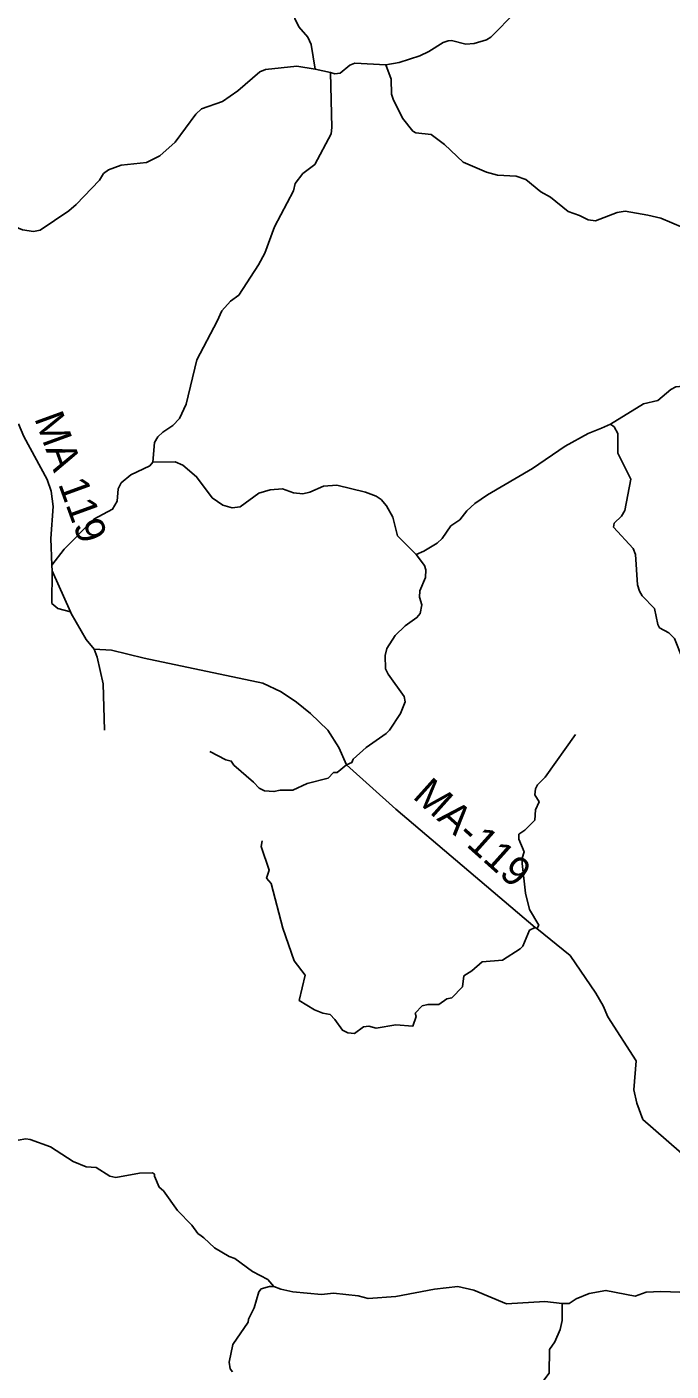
# Model space of a CAD drawing. Extents: x 332 to 501, y 9447 to 9559.
# Drawn here: x 475.23 to 483.56, y 9494.28 to 9511.64 of the extents above; entities that cross this region are included whole.
import ezdxf

# ---------------------------------------------------------------- set-up
doc = ezdxf.new("R2010")
doc.units = 0
for name, color, linetype in [('Level 2', 7, 'Continuous'), ('Level 31', 7, 'Continuous'), ('Level 4', 7, 'Continuous'), ('Level 5', 7, 'Continuous'), ('Level 6', 7, 'Continuous')]:
    doc.layers.add(name, color=color, linetype=linetype)

msp = doc.modelspace()

# ---------------------------------------------------------------- linework, layer by layer
at = {"layer": 'Level 2'}
for points in [[(479.3623, 9502.1083), (479.2662, 9502.3325), (479.1221, 9502.5596)], [(480, 9501.5363), (479.3623, 9502.1083)], [(481.8041, 9500.0098), (480, 9501.5363)], [(481.8168, 9500), (481.8041, 9500.0098)], [(481.8249, 9499.9937), (481.8168, 9500)], [(484, 9496.8247), (483.1916, 9497.5294), (483.1148, 9497.7406), (483.0763, 9497.9134), (483.1084, 9498.2847), (482.7391, 9498.8538), (482.6815, 9498.9947), (482.5855, 9499.1612), (482.2526, 9499.648), (481.8249, 9499.9937)], [(484, 9495.2529), (483.7972, 9495.2917), (483.4254, 9495.3065), (483.2376, 9495.2991), (483.0958, 9495.2475), (482.7167, 9495.3212), (482.4994, 9495.2807), (482.3338, 9495.2107), (482.2417, 9495.1518), (482.1514, 9495.1518)]]:
    msp.add_lwpolyline(points, dxfattribs=at)
at = {"layer": 'Level 4'}
for points in [[(475.1276, 9506.5158), (475.1968, 9506.3519), (475.4947, 9505.794), (475.5502, 9505.6451), (475.5755, 9505.4482), (475.5452, 9505.0342), (475.557, 9504.6897)], [(475.557, 9504.6897), (475.5629, 9504.6152)], [(475.5629, 9504.6152), (475.7988, 9504.0846)], [(475.7988, 9504.0846), (475.807, 9504.0668)], [(475.807, 9504.0668), (475.9996, 9503.7272), (476.1056, 9503.6029)], [(476.1056, 9503.6029), (476.3278, 9503.5928), (476.7518, 9503.4893), (478.2815, 9503.1637), (478.5213, 9503.0533), (478.7176, 9502.9201), (478.8999, 9502.7712), (479.1221, 9502.5596)], [(475.9999, 9496.9153), (475.8325, 9496.9871), (475.5416, 9497.175), (475.2766, 9497.2707), (475.2213, 9497.2781), (474.8211, 9497.2098), (474.5634, 9497.2098), (474.453, 9497.254), (474.2763, 9497.3718), (474.1916, 9497.4639), (474.129, 9497.5818), (473.9965, 9497.6518), (473.8087, 9497.6665), (473.4811, 9497.4455), (473.3319, 9497.3866), (472.9896, 9497.2761), (472.8165, 9497.254), (472.6803, 9497.2577), (472.4226, 9497.125), (472.2496, 9497.1066), (471.9999, 9497.0062)], [(476.8832, 9496.7968), (476.8832, 9496.8225), (476.8559, 9496.8397), (476.6903, 9496.8361), (476.3847, 9496.7808), (476.3074, 9496.7955), (476.1307, 9496.9097), (475.9999, 9496.9153)], [(477.4861, 9496.026), (477.4428, 9496.0563), (477.3655, 9496.1632), (477.1814, 9496.351), (477.001, 9496.6052), (476.9421, 9496.6531), (476.8832, 9496.7968)], [(477.522, 9496), (477.4861, 9496.026)], [(478.4263, 9495.373), (478.3474, 9495.4612), (478.1486, 9495.5643), (477.9214, 9495.7322), (477.8478, 9495.7579), (477.66, 9495.8685), (477.522, 9496)], [(480, 9495.2429), (479.6462, 9495.2144), (479.5137, 9495.2512), (479.1971, 9495.2844), (479.0424, 9495.266), (478.6706, 9495.3028), (478.5167, 9495.3359), (478.4263, 9495.373)], [(482.1514, 9495.1518), (481.9266, 9495.1775), (481.4333, 9495.1481), (481.0099, 9495.3249), (480.8037, 9495.3691), (480.5018, 9495.3359), (480, 9495.2429)]]:
    msp.add_lwpolyline(points, dxfattribs=at)
at = {"layer": 'Level 5'}
for points in [[(479.8705, 9511.1532), (480.0434, 9511.1808), (480.3122, 9511.2704), (480.4296, 9511.3234), (480.6115, 9511.442), (480.6772, 9511.4635), (480.7226, 9511.466), (480.9068, 9511.4206), (481.0141, 9511.4269), (481.1744, 9511.4761), (481.2274, 9511.5108), (481.5505, 9511.8377), (481.6735, 9511.9073)], [(474.888, 9509.1414), (475.1766, 9509.0213), (475.3212, 9509.0005), (475.4064, 9509.0187), (475.7749, 9509.2648), (475.8733, 9509.3482), (476.1712, 9509.6612), (476.2267, 9509.7483), (476.2886, 9509.7962), (476.4515, 9509.8555), (476.7821, 9509.8908), (476.9537, 9509.9754), (477.1493, 9510.1534), (477.4169, 9510.515), (477.4926, 9510.5844), (477.7609, 9510.6771), (477.9596, 9510.8167), (478.2455, 9511.0621), (478.3169, 9511.0937)], [(478.3169, 9511.0937), (478.7245, 9511.1341), (478.9589, 9511.0982)], [(478.9589, 9511.0982), (479.1592, 9511.0533)], [(479.1592, 9511.0533), (479.2155, 9511.0369), (479.2836, 9511.0445), (479.4073, 9511.148), (479.4717, 9511.1744), (479.8705, 9511.1532)], [(481.6816, 9509.6709), (481.5566, 9509.712), (481.3146, 9509.7284), (481.1741, 9509.7659), (480.8712, 9509.8947), (480.6323, 9510.1243), (480.4589, 9510.2516), (480.259, 9510.2719), (480.2215, 9510.2937), (480.0872, 9510.4616), (479.967, 9510.7083), (479.9451, 9510.7731), (479.942, 9510.9667), (479.8705, 9511.1532)], [(481.8762, 9509.5139), (481.6816, 9509.6709)], [(482.8611, 9509.2465), (482.5826, 9509.1389), (482.4873, 9509.1483), (482.3764, 9509.2076), (482.2296, 9509.2568), (482.0001, 9509.4411), (481.8762, 9509.5139)], [(483.2561, 9509.2105), (482.9652, 9509.26), (482.8611, 9509.2465)], [(485.4436, 9507.794), (485.1247, 9508.2535), (484.9326, 9508.5822), (484.8421, 9508.6806), (484.7468, 9508.7477), (484.141, 9508.9515), (483.71, 9509.0491), (483.4258, 9509.1732), (483.2561, 9509.2105)], [(480.2657, 9504.8276), (480.3656, 9504.8698), (480.5358, 9504.9729), (480.5999, 9505.0322), (480.714, 9505.1985), (480.8295, 9505.275), (480.9185, 9505.3921)], [(480.2657, 9504.8276), (480.0252, 9505.0689), (479.9612, 9505.3102)], [(482.8162, 9505.1792), (483.0684, 9504.9056), (483.0997, 9504.826), (483.1247, 9504.434), (483.1497, 9504.352), (483.1856, 9504.2942), (483.3433, 9504.1287), (483.387, 9503.9218), (483.4104, 9503.8797), (483.5307, 9503.8156), (483.6025, 9503.7407), (483.8008, 9503.2418)], [(480.311, 9504.3584), (480.3844, 9504.5286), (480.3891, 9504.627), (480.3703, 9504.6832), (480.2657, 9504.8276)], [(475.6339, 9504.1314), (475.5584, 9504.1949), (475.5629, 9504.6152)], [(479.9198, 9502.5598), (480.0635, 9502.7717), (480.1213, 9502.9232), (480.1103, 9502.9935), (479.9011, 9503.2832), (479.8699, 9503.3503), (479.862, 9503.5205), (479.8854, 9503.6119), (479.9916, 9503.7821), (480.1228, 9503.9039), (480.2743, 9504.0124), (480.3149, 9504.064), (480.3383, 9504.1748), (480.3055, 9504.2748), (480.311, 9504.3584)], [(475.7988, 9504.0846), (475.6339, 9504.1314)], [(476.1056, 9503.6029), (476.143, 9503.4989), (476.2185, 9503.1573), (476.2383, 9502.5588)], [(479.9198, 9502.5598), (479.8779, 9502.5155), (479.6183, 9502.3339), (479.4519, 9502.1849), (479.4344, 9502.1411), (479.3623, 9502.1083)], [(482.3225, 9502.5013), (481.9306, 9501.9492), (481.8343, 9501.8528), (481.808, 9501.8002), (481.7993, 9501.7213), (481.8518, 9501.6337), (481.808, 9501.5285), (481.7993, 9501.397), (481.6679, 9501.2656), (481.589, 9501.213), (481.589, 9501.1516), (481.6591, 9500.9851), (481.6328, 9500.9062), (481.6328, 9500.8361), (481.6766, 9500.4505), (481.7292, 9500.2402), (481.8491, 9500.0374), (481.8286, 9500)], [(478.3045, 9501.773), (478.2345, 9501.8081), (478.1644, 9501.8869), (477.9104, 9502.106), (477.8753, 9502.1586), (477.8053, 9502.1761), (477.5975, 9502.2813)], [(479.3623, 9502.1083), (479.2417, 9502.0096), (479.1979, 9502.0096), (479.1278, 9501.9395), (478.8563, 9501.8694), (478.6724, 9501.7818), (478.506, 9501.7818), (478.4271, 9501.7642), (478.3045, 9501.773)], [(481.7305, 9499.9754), (481.6416, 9499.7687), (481.6066, 9499.7336), (481.3788, 9499.5846), (481.1161, 9499.5671), (480.9822, 9499.4488), (480.8784, 9499.3829), (480.8621, 9499.2428), (480.7232, 9499.0994), (480.6606, 9499.0851), (480.5555, 9499.015), (480.4154, 9499.015), (480.3408, 9498.9949), (480.2498, 9498.9008)], [(481.7305, 9499.9754), (481.8041, 9500.0098)], [(482.1514, 9495.1518), (482.1514, 9494.9312), (482.1232, 9494.816), (482.0577, 9494.6579), (481.9877, 9494.5585), (481.9837, 9494.2513), (481.5459, 9493.676), (481.4595, 9493.5958), (481.4194, 9493.4842), (481.4041, 9493.3245), (481.3651, 9493.2636), (481.345, 9493.1773), (481.4232, 9493.0348), (481.4418, 9492.8958), (481.5097, 9492.7647), (481.4808, 9492.4204), (481.5601, 9491.5793), (481.6136, 9491.3652), (481.7029, 9491.2251), (481.8417, 9491.0797), (481.8354, 9491.0358), (481.9326, 9490.9062), (481.9023, 9490.8503), (481.9598, 9490.8192)]]:
    msp.add_lwpolyline(points, dxfattribs=at)
at = {"layer": 'Level 6'}
for points in [[(478.0732, 9513.8135), (478.1943, 9513.6239), (478.2648, 9513.4721), (478.359, 9513.341), (478.5872, 9512.8945), (478.6398, 9512.7586), (478.6924, 9512.3825), (478.6954, 9511.7493), (478.747, 9511.6411), (478.8661, 9511.5091), (478.9078, 9511.4168), (478.9589, 9511.0982)], [(478.4347, 9509.0591), (478.6788, 9509.5262), (478.6999, 9509.6196), (478.7995, 9509.7477), (478.9563, 9509.8652), (479.166, 9510.2595), (479.176, 9510.3439), (479.1592, 9511.0533)], [(477.6947, 9507.8417), (477.7554, 9507.9729), (477.864, 9508.0985), (477.9725, 9508.1748), (478.2258, 9508.5696), (478.3096, 9508.7207), (478.4347, 9509.0591)], [(476.8629, 9506.0189), (476.883, 9506.272), (476.9252, 9506.3464), (476.9896, 9506.4087), (477.1222, 9506.4931), (477.2046, 9506.5845), (477.2911, 9506.7674), (477.4318, 9507.343), (477.6947, 9507.8417)], [(482.7767, 9506.5117), (483.201, 9506.7738), (483.3879, 9506.816), (483.5528, 9506.9576), (483.6212, 9506.9918), (483.7559, 9507.0038), (483.8664, 9506.9878), (484.0253, 9507.0531), (484.1801, 9507.0872), (484.4957, 9507.2229), (484.6283, 9507.2008), (484.8455, 9507.2419), (485.1088, 9507.3906), (485.2455, 9507.5182), (485.34, 9507.5805), (485.4023, 9507.6046), (485.5211, 9507.6134)], [(480.9185, 9505.3921), (481.0217, 9505.4857), (481.1846, 9505.5982), (481.7655, 9505.9378), (482.1897, 9506.2242), (482.4873, 9506.392), (482.6602, 9506.4601)], [(482.6602, 9506.4601), (482.7767, 9506.5117)], [(482.8162, 9505.1792), (482.8223, 9505.2298), (482.9157, 9505.3212), (482.9594, 9505.3967), (483.0388, 9505.8), (482.872, 9506.1358), (482.868, 9506.3881), (482.8223, 9506.4776), (482.7767, 9506.5117)], [(476.4134, 9505.6766), (476.4544, 9505.7515), (476.5765, 9505.8548), (476.8227, 9505.973), (476.8629, 9506.0189)], [(479.9612, 9505.3102), (479.8831, 9505.4552), (479.8107, 9505.5376), (479.7464, 9505.5818), (479.6118, 9505.6321), (479.2381, 9505.7215), (479.0673, 9505.7084), (478.8925, 9505.6301), (478.8, 9505.612), (478.6815, 9505.6251), (478.5388, 9505.6733), (478.38, 9505.6632), (478.2333, 9505.618), (477.9902, 9505.4432), (477.8857, 9505.4281), (477.7672, 9505.4623), (477.6305, 9505.5607), (477.4276, 9505.831), (477.2508, 9505.9797), (477.1523, 9506.0219), (476.8629, 9506.0189)], [(475.557, 9504.6897), (475.7172, 9504.8941), (476.0981, 9505.2816), (476.3422, 9505.4108), (476.4028, 9505.5141), (476.4134, 9505.6766)], [(478.2748, 9501.1281), (478.2607, 9501.057), (478.3658, 9500.7502), (478.3308, 9500.6451), (478.3921, 9500.575), (478.5414, 9500)], [(478.5414, 9500), (478.6899, 9499.5759), (478.8301, 9499.3918), (478.7512, 9499.0675), (478.9527, 9498.9449), (479.0578, 9498.901), (479.1541, 9498.8835), (479.2154, 9498.8222), (479.3118, 9498.6819), (479.3818, 9498.6469), (479.4694, 9498.6381), (479.5833, 9498.7258), (479.6534, 9498.7345), (479.7497, 9498.7082), (480, 9498.7499)], [(481.8286, 9500), (481.8249, 9499.9937)], [(480, 9498.7499), (480.2227, 9498.7345), (480.2665, 9498.8572), (480.2498, 9498.9008)], [(478.4263, 9495.373), (478.3701, 9495.373), (478.2627, 9495.3423), (478.2321, 9495.3015), (478.173, 9495.0959), (478.0987, 9494.9474), (478.0941, 9494.9103), (477.8945, 9494.6203), (477.8481, 9494.394), (477.862, 9494.3058), (477.8899, 9494.2686)]]:
    msp.add_lwpolyline(points, dxfattribs=at)

# ---------------------------------------------------------------- texts
at = {"layer": 'Level 31'}
for s, rotation, p in [('MA 119', 289.98311, (475.3273, 9506.5886)), ('MA-119', 318.15949, (480.2061, 9501.689))]:
    msp.add_text(s, height=0.38, rotation=rotation, dxfattribs=at).set_placement(p)

doc.saveas('drawing.dxf')
